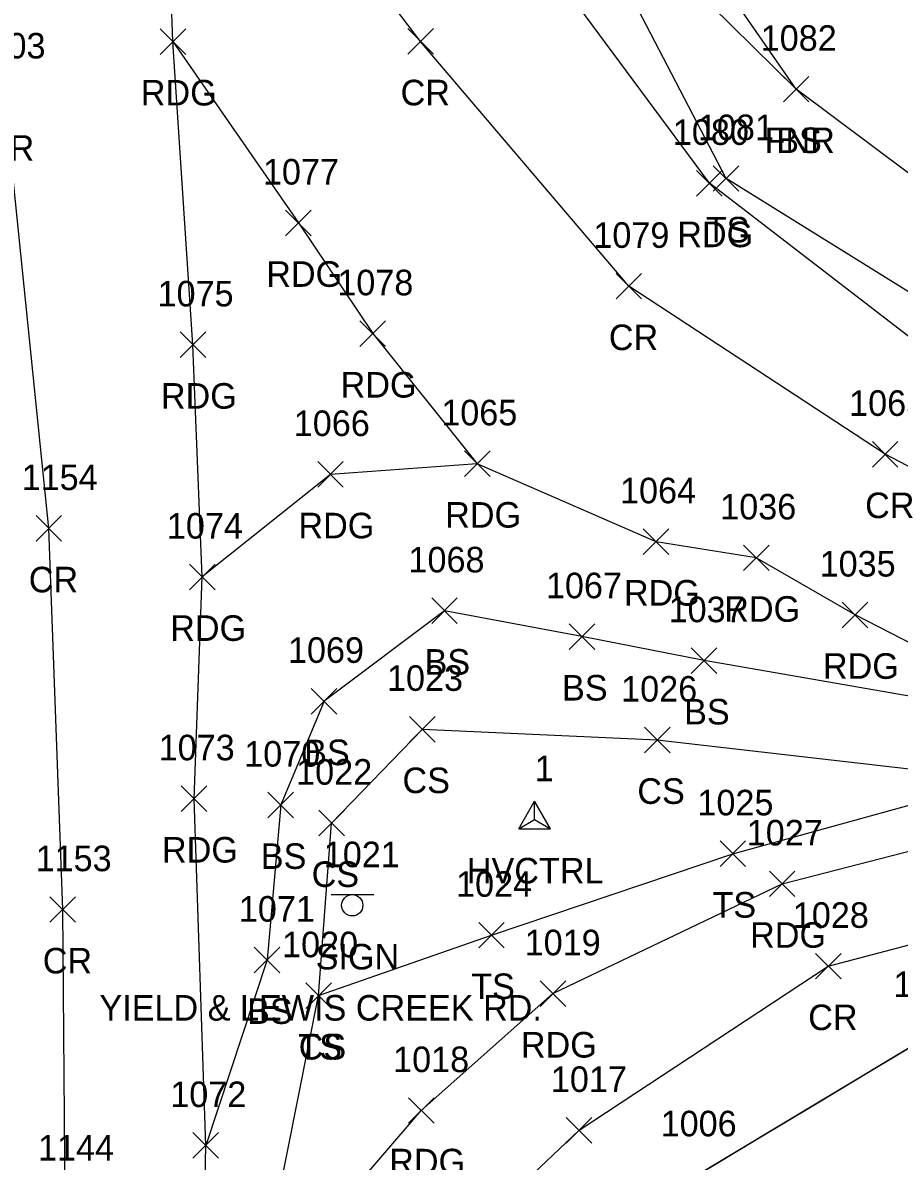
# Model space of a CAD drawing. Extents: x 1459992 to 1461532, y 647785 to 648535.
# Drawn here: x 1461396.4 to 1461465, y 647878.7 to 647967.8 of the extents above; entities that cross this region are included whole.
import ezdxf

# ---------------------------------------------------------------- set-up
doc = ezdxf.new("R2010")
doc.units = 0
for name, color, linetype in [('C_A', 7, 'Continuous'), ('C_I', 7, 'Continuous'), ('CPSM', 7, 'Continuous'), ('L_A', 7, 'Continuous'), ('L_I', 7, 'Continuous'), ('L_TIC', 7, 'Continuous'), ('LELB', 7, 'Continuous'), ('LFNC', 7, 'Continuous'), ('LSOGP', 7, 'Continuous'), ('P_A', 7, 'Continuous'), ('P_I', 7, 'Continuous'), ('P_TIC', 7, 'Continuous'), ('PEU', 7, 'Continuous'), ('PRC', 7, 'Continuous'), ('S_A', 7, 'Continuous'), ('S_C', 7, 'Continuous'), ('S_I', 7, 'Continuous'), ('SSGN', 7, 'Continuous')]:
    doc.layers.add(name, color=color, linetype=linetype)

msp = doc.modelspace()

# ---------------------------------------------------------------- linework, layer by layer
at = {"layer": 'CPSM'}
for p, q in [((1461435.216, 647904.72), (1461436.466, 647906.885)), ((1461437.716, 647904.72), (1461436.466, 647906.885)), ((1461436.466, 647905.441), (1461436.466, 647906.885)), ((1461435.216, 647904.72), (1461436.466, 647905.441)), ((1461436.466, 647905.441), (1461436.466, 647905.441)), ((1461436.466, 647905.441), (1461437.716, 647904.72)), ((1461435.216, 647904.72), (1461437.716, 647904.72))]:
    msp.add_line(p, q, dxfattribs=at)
at = {"layer": 'L_TIC'}
for points in [[(1461455.928, 647961.574), (1461457.928, 647963.574)], [(1461457.928, 647961.574), (1461455.928, 647963.574)], [(1461455.928, 647961.574), (1461457.928, 647963.574)], [(1461457.928, 647961.574), (1461455.928, 647963.574)], [(1461450.446, 647954.583), (1461452.446, 647956.583)], [(1461452.446, 647954.583), (1461450.446, 647956.583)], [(1461428.412, 647920.772), (1461430.412, 647922.772)], [(1461430.412, 647920.772), (1461428.412, 647922.772)], [(1461439.167, 647918.749), (1461441.167, 647920.749)], [(1461441.167, 647918.749), (1461439.167, 647920.749)], [(1461448.72, 647916.876), (1461450.72, 647918.876)], [(1461450.72, 647916.876), (1461448.72, 647918.876)], [(1461418.989, 647913.696), (1461420.989, 647915.696)], [(1461420.989, 647913.696), (1461418.989, 647915.696)], [(1461426.682, 647911.506), (1461428.682, 647913.506)], [(1461428.682, 647911.506), (1461426.682, 647913.506)], [(1461445.061, 647910.666), (1461447.061, 647912.666)], [(1461447.061, 647910.666), (1461445.061, 647912.666)], [(1461415.597, 647905.58), (1461417.597, 647907.58)], [(1461417.597, 647905.58), (1461415.597, 647907.58)], [(1461419.574, 647904.167), (1461421.574, 647906.167)], [(1461421.574, 647904.167), (1461419.574, 647906.167)], [(1461450.975, 647901.767), (1461452.975, 647903.767)], [(1461452.975, 647901.767), (1461450.975, 647903.767)], [(1461432.088, 647895.397), (1461434.088, 647897.397)], [(1461434.088, 647895.397), (1461432.088, 647897.397)], [(1461414.526, 647893.455), (1461416.526, 647895.455)], [(1461416.526, 647893.455), (1461414.526, 647895.455)], [(1461418.562, 647890.668), (1461420.562, 647892.668)], [(1461420.562, 647890.668), (1461418.562, 647892.668)], [(1461418.562, 647890.668), (1461420.562, 647892.668)], [(1461420.562, 647890.668), (1461418.562, 647892.668)], [(1461409.725, 647878.948), (1461411.725, 647880.948)], [(1461411.725, 647878.948), (1461409.725, 647880.948)]]:
    msp.add_lwpolyline(points, dxfattribs=at)
at = {"layer": 'LELB'}
for points in [[(1461456.928, 647962.574), (1461441.844, 647977.438), (1461429.255, 647993.418), (1461419.691, 648013.412), (1461411.308, 648032.792), (1461409.621, 648042.868), (1461413.323, 648043.053), (1461411.254, 648075.168)], [(1461520.469, 647921.947), (1461496.948, 647928.774), (1461471.443, 647943.184), (1461451.446, 647955.583), (1461439.999, 647977.602), (1461425.412, 647991.396), (1461416.238, 648011.602), (1461408.429, 648031.646)], [(1461478.08, 647912.963), (1461449.72, 647917.876), (1461440.167, 647919.749), (1461429.412, 647921.772), (1461419.989, 647914.696), (1461416.597, 647906.58), (1461415.526, 647894.455), (1461410.725, 647879.948)], [(1461419.562, 647891.668), (1461420.574, 647905.167), (1461427.682, 647912.506), (1461446.061, 647911.666), (1461473.056, 647908.58)], [(1461414.798, 647867.804), (1461419.562, 647891.668), (1461433.088, 647896.397), (1461451.975, 647902.767), (1461473.056, 647908.58), (1461481.61, 647907.91)]]:
    msp.add_lwpolyline(points, dxfattribs=at)
at = {"layer": 'LFNC'}
msp.add_lwpolyline([(1461474.617, 647949.345), (1461456.928, 647962.574), (1461445.036, 647979.718), (1461443.789, 647990.405), (1461433.969, 647995.531), (1461430.825, 648006.278), (1461422.904, 648014.499), (1461423.391, 648024.166), (1461415.941, 648033.218)], dxfattribs=at)
at = {"layer": 'LSOGP'}
msp.add_lwpolyline([(1461449.23, 647877.66), (1461453.771, 647880.383), (1461458.311, 647883.107), (1461462.852, 647885.831), (1461467.393, 647888.554), (1461472.231, 647889.899), (1461477.07, 647891.243), (1461481.908, 647892.588), (1461486.747, 647893.933), (1461492.984, 647894.606), (1461499.221, 647895.28), (1461505.459, 647895.953), (1461512.701, 647891.607), (1461512.269, 647892.995), (1461511.696, 647896.627), (1461515.675, 647905.406), (1461517.549, 647912.177), (1461519.489, 647918.714), (1461520.469, 647921.947), (1461522.06, 647928.395), (1461521.642, 647930.202), (1461522.584, 647947.27), (1461523.894, 647961.904), (1461528.68, 647974.065)], dxfattribs=at)
at = {"layer": 'P_TIC'}
for points in [[(1461407.158, 647965.296), (1461409.158, 647967.296)], [(1461409.158, 647965.296), (1461407.158, 647967.296)], [(1461407.158, 647965.296), (1461409.158, 647967.296)], [(1461409.158, 647965.296), (1461407.158, 647967.296)], [(1461426.543, 647965.309), (1461428.543, 647967.309)], [(1461428.543, 647965.309), (1461426.543, 647967.309)], [(1461449.141, 647954.213), (1461451.141, 647956.213)], [(1461451.141, 647954.213), (1461449.141, 647956.213)], [(1461416.975, 647951.111), (1461418.975, 647953.111)], [(1461418.975, 647951.111), (1461416.975, 647953.111)], [(1461442.839, 647946.161), (1461444.839, 647948.161)], [(1461444.839, 647946.161), (1461442.839, 647948.161)], [(1461422.794, 647942.448), (1461424.794, 647944.448)], [(1461424.794, 647942.448), (1461422.794, 647944.448)], [(1461408.729, 647941.579), (1461410.729, 647943.579)], [(1461410.729, 647941.579), (1461408.729, 647943.579)], [(1461430.977, 647932.274), (1461432.977, 647934.274)], [(1461432.977, 647932.274), (1461430.977, 647934.274)], [(1461462.894, 647933.017), (1461464.894, 647935.017)], [(1461464.894, 647933.017), (1461462.894, 647935.017)], [(1461419.49, 647931.438), (1461421.49, 647933.438)], [(1461421.49, 647931.438), (1461419.49, 647933.438)], [(1461397.446, 647927.211), (1461399.446, 647929.211)], [(1461399.446, 647927.211), (1461397.446, 647929.211)], [(1461444.967, 647926.176), (1461446.967, 647928.176)], [(1461446.967, 647926.176), (1461444.967, 647928.176)], [(1461452.814, 647924.913), (1461454.814, 647926.913)], [(1461454.814, 647924.913), (1461452.814, 647926.913)], [(1461409.459, 647923.415), (1461411.459, 647925.415)], [(1461411.459, 647923.415), (1461409.459, 647925.415)], [(1461409.459, 647923.415), (1461411.459, 647925.415)], [(1461411.459, 647923.415), (1461409.459, 647925.415)], [(1461460.538, 647920.448), (1461462.538, 647922.448)], [(1461462.538, 647920.448), (1461460.538, 647922.448)], [(1461408.816, 647906.073), (1461410.816, 647908.073)], [(1461410.816, 647906.073), (1461408.816, 647908.073)], [(1461454.838, 647899.411), (1461456.838, 647901.411)], [(1461456.838, 647899.411), (1461454.838, 647901.411)], [(1461398.539, 647897.401), (1461400.539, 647899.401)], [(1461400.539, 647897.401), (1461398.539, 647899.401)], [(1461458.44, 647892.969), (1461460.44, 647894.969)], [(1461460.44, 647892.969), (1461458.44, 647894.969)], [(1461436.899, 647890.821), (1461438.899, 647892.821)], [(1461438.899, 647890.821), (1461436.899, 647892.821)], [(1461426.597, 647881.684), (1461428.597, 647883.684)], [(1461428.597, 647881.684), (1461426.597, 647883.684)], [(1461438.941, 647880.132), (1461440.941, 647882.132)], [(1461440.941, 647880.132), (1461438.941, 647882.132)], [(1461409.725, 647878.948), (1461411.725, 647880.948)], [(1461411.725, 647878.948), (1461409.725, 647880.948)]]:
    msp.add_lwpolyline(points, dxfattribs=at)
at = {"layer": 'PEU'}
for points in [[(1461511.696, 647896.627), (1461486.747, 647893.933), (1461467.393, 647888.554), (1461449.23, 647877.66), (1461431.428, 647862.669), (1461417.103, 647833.705), (1461412.59, 647812.047), (1461410.586, 647789.715), (1461409.995, 647812.297), (1461409.762, 647834.293), (1461410.349, 647859.704), (1461410.725, 647879.948), (1461409.816, 647907.073), (1461410.459, 647924.415), (1461409.729, 647942.579), (1461408.158, 647966.296), (1461407.047, 647997.095), (1461405.272, 648031.274), (1461404.297, 648042.515)], [(1461519.489, 647918.714), (1461495.544, 647925.359), (1461469.2, 647940.569), (1461450.141, 647955.213), (1461436.65, 647973.461), (1461421.869, 647989.547), (1461413.971, 648010.655), (1461405.272, 648031.274)], [(1461408.158, 647966.296), (1461417.975, 647952.111), (1461423.794, 647943.448)], [(1461423.794, 647943.448), (1461431.977, 647933.274)], [(1461410.349, 647859.704), (1461414.798, 647867.804), (1461427.597, 647882.684), (1461437.899, 647891.821), (1461455.838, 647900.411), (1461474.569, 647905.238), (1461481.61, 647907.91), (1461493.486, 647909.89), (1461478.08, 647912.963), (1461461.538, 647921.448), (1461453.814, 647925.913), (1461445.967, 647927.176), (1461431.977, 647933.274), (1461420.49, 647932.438), (1461410.459, 647924.415)]]:
    msp.add_lwpolyline(points, dxfattribs=at)
at = {"layer": 'PRC'}
for points in [[(1461399.102, 647801.607), (1461400.203, 647838.194), (1461399.73, 647875.765), (1461399.539, 647898.401), (1461398.446, 647928.211), (1461395.012, 647961.974), (1461394.123, 647993.813), (1461392.15, 648024.041), (1461390.381, 648057.367), (1461388.518, 648080.662), (1461387.016, 648100.033), (1461383.866, 648115.79), (1461378.351, 648129.267), (1461372.213, 648140.65), (1461365.441, 648150.969), (1461358.126, 648158.61)], [(1461517.549, 647912.177), (1461492.879, 647918.878), (1461463.894, 647934.017), (1461443.839, 647947.161), (1461427.543, 647966.309), (1461418.129, 647978.725), (1461407.047, 647997.095)], [(1461409.762, 647834.293), (1461419.514, 647857.614), (1461429.199, 647870.944), (1461439.941, 647881.132), (1461459.44, 647893.969), (1461476.688, 647898.52), (1461483.024, 647900.511), (1461497.869, 647903.569), (1461515.675, 647905.406)]]:
    msp.add_lwpolyline(points, dxfattribs=at)
at = {"layer": 'SSGN'}
for p, q in [((1461420.544, 647899.566), (1461423.878, 647899.566)), ((1461422.191, 647898.733), (1461422.191, 647898.733))]:
    msp.add_line(p, q, dxfattribs=at)
msp.add_circle((1461422.191, 647898.733), 0.833, dxfattribs=at)

# ---------------------------------------------------------------- texts
at = {"layer": 'C_A'}
msp.add_text('HVCTRL', height=2, dxfattribs=at).set_placement((1461431.159, 647900.441))
at = {"layer": 'C_I'}
msp.add_text('1', height=2, dxfattribs=at).set_placement((1461436.466, 647908.441))
at = {"layer": 'L_A'}
for s, p in [('FNR', (1461454.463, 647957.574)), ('BS', (1461455.369, 647957.574)), ('TS', (1461449.856, 647950.583)), ('BS', (1461427.853, 647916.772)), ('BS', (1461438.608, 647914.749)), ('BS', (1461448.161, 647912.876)), ('BS', (1461418.43, 647909.696)), ('CS', (1461426.123, 647907.506)), ('CS', (1461444.502, 647906.666)), ('BS', (1461415.038, 647901.58)), ('CS', (1461419.015, 647900.167)), ('TS', (1461450.384, 647897.767)), ('TS', (1461431.498, 647891.397)), ('BS', (1461413.967, 647889.455)), ('TS', (1461417.972, 647886.668)), ('CS', (1461418.003, 647886.668))]:
    msp.add_text(s, height=2, dxfattribs=at).set_placement(p)
at = {"layer": 'L_I'}
for s, p in [('1082', (1461454.156, 647965.574)), ('1082', (1461454.156, 647965.574)), ('1081', (1461449.242, 647958.583)), ('1068', (1461426.593, 647924.772)), ('1067', (1461437.348, 647922.749)), ('1037', (1461446.949, 647920.876)), ('1069', (1461417.162, 647917.696)), ('1023', (1461424.911, 647915.506)), ('1026', (1461443.235, 647914.666)), ('1070', (1461413.739, 647909.58)), ('1022', (1461417.802, 647908.167)), ('1025', (1461449.203, 647905.767)), ('1024', (1461430.317, 647899.397)), ('1071', (1461413.321, 647897.455)), ('1020', (1461416.704, 647894.668)), ('1020', (1461416.704, 647894.668)), ('1072', (1461407.953, 647882.948))]:
    msp.add_text(s, height=2, dxfattribs=at).set_placement(p)
at = {"layer": 'P_A'}
for s, p in [('RDG', (1461405.647, 647961.296)), ('RDG', (1461405.647, 647961.296)), ('CR', (1461425.976, 647961.309)), ('CR', (1461393.445, 647956.974)), ('RDG', (1461447.629, 647950.213)), ('RDG', (1461415.463, 647947.111)), ('CR', (1461442.272, 647942.161)), ('RDG', (1461421.283, 647938.448)), ('RDG', (1461407.217, 647937.579)), ('CR', (1461462.327, 647929.017)), ('RDG', (1461429.465, 647928.274)), ('RDG', (1461417.979, 647927.438)), ('CR', (1461396.88, 647923.211)), ('RDG', (1461443.455, 647922.176)), ('RDG', (1461451.302, 647920.913)), ('RDG', (1461407.947, 647919.415)), ('RDG', (1461407.947, 647919.415)), ('RDG', (1461459.026, 647916.448)), ('RDG', (1461407.304, 647902.073)), ('RDG', (1461453.326, 647895.411)), ('CR', (1461397.973, 647893.401)), ('CR', (1461457.873, 647888.969)), ('RDG', (1461435.387, 647886.821)), ('RDG', (1461425.085, 647877.684))]:
    msp.add_text(s, height=2, dxfattribs=at).set_placement(p)
at = {"layer": 'P_I'}
for s, p in [('1203', (1461392.241, 647964.974)), ('1080', (1461447.283, 647958.213)), ('1077', (1461415.203, 647955.111)), ('1079', (1461441.059, 647950.161)), ('1078', (1461421.023, 647946.448)), ('1075', (1461406.958, 647945.579)), ('1063', (1461461.075, 647937.017)), ('1065', (1461429.158, 647936.274)), ('1066', (1461417.616, 647935.438)), ('1154', (1461396.32, 647931.211)), ('1064', (1461443.148, 647930.176)), ('1036', (1461450.987, 647928.913)), ('1074', (1461407.687, 647927.415)), ('1074', (1461407.687, 647927.415)), ('1035', (1461458.766, 647924.448)), ('1073', (1461407.044, 647910.073)), ('1027', (1461453.066, 647903.411)), ('1153', (1461397.414, 647901.401)), ('1028', (1461456.669, 647896.969)), ('1019', (1461435.686, 647894.821)), ('1005', (1461464.542, 647891.554)), ('1018', (1461425.392, 647885.684)), ('1017', (1461437.736, 647884.132)), ('1072', (1461407.953, 647882.948)), ('1006', (1461446.325, 647880.66)), ('1144', (1461397.604, 647878.765))]:
    msp.add_text(s, height=2, dxfattribs=at).set_placement(p)
at = {"layer": 'S_A'}
msp.add_text('SIGN', height=2, dxfattribs=at).set_placement((1461419.329, 647893.713))
at = {"layer": 'S_C'}
msp.add_text('YIELD & LEWIS CREEK RD.', height=2, dxfattribs=at).set_placement((1461402.408, 647889.713))
at = {"layer": 'S_I'}
msp.add_text('1021', height=2, dxfattribs=at).set_placement((1461419.967, 647901.713))

doc.saveas('drawing.dxf')
